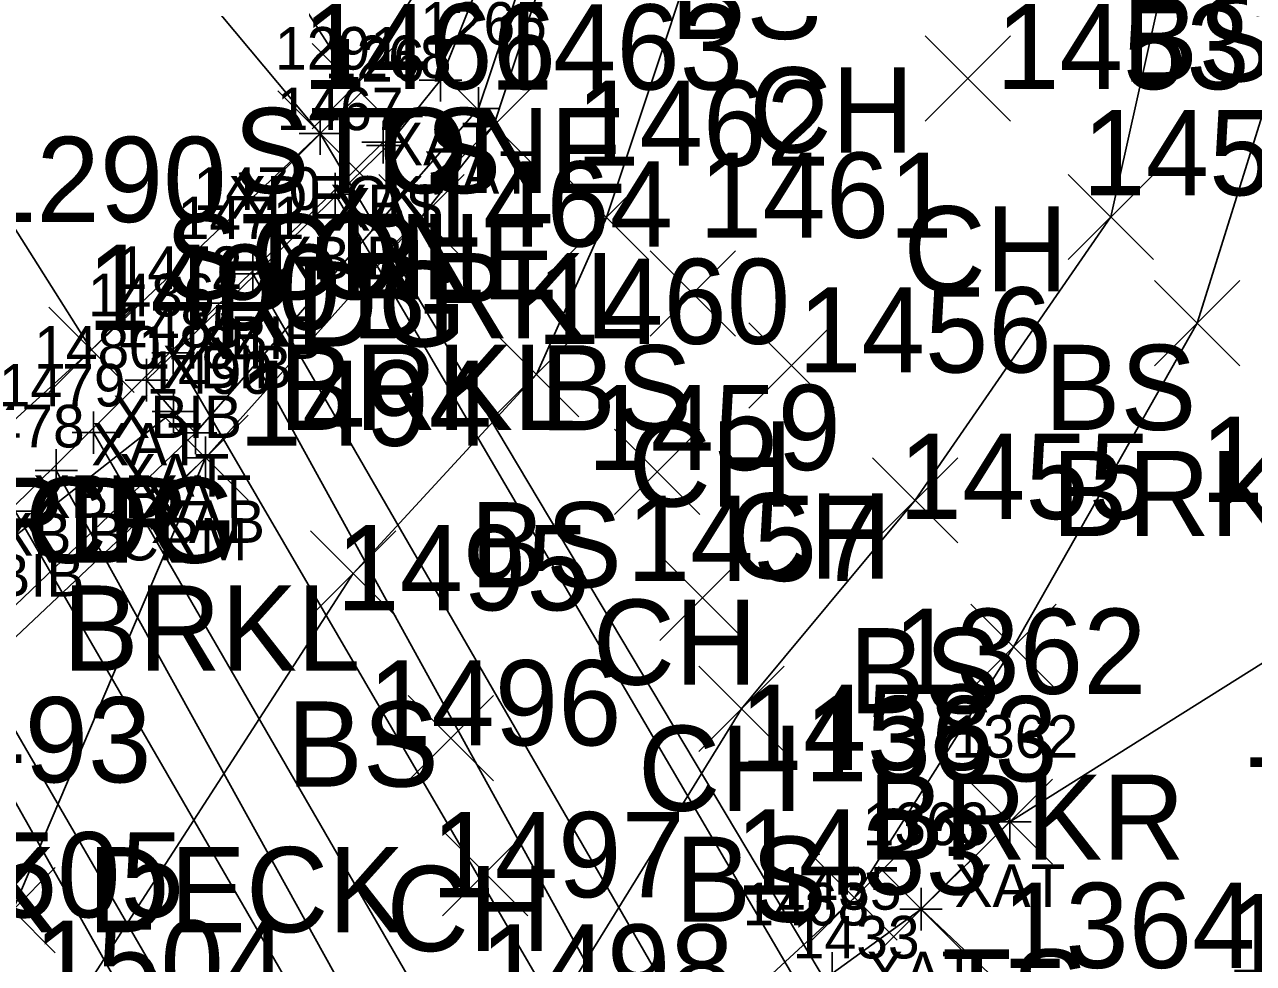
# Model space of a CAD drawing. Extents: x 1441651 to 1442140, y 243798 to 245625.
# Drawn here: x 1442046.7 to 1442075.54, y 245404.9 to 245426.94 of the extents above; entities that cross this region are included whole.
import ezdxf

# ---------------------------------------------------------------- set-up
doc = ezdxf.new("R2010")
doc.units = 0
for name, color, linetype in [('B_A', 7, 'Continuous'), ('B_C', 7, 'Continuous'), ('B_I', 7, 'Continuous'), ('B_TIC', 7, 'Continuous'), ('BB', 7, 'Continuous'), ('BELB', 7, 'Continuous'), ('BSE', 7, 'Continuous'), ('BSUBM', 7, 'Continuous'), ('L_A', 7, 'Continuous'), ('L_I', 7, 'Continuous'), ('L_TIC', 7, 'Continuous'), ('LASF', 7, 'Continuous'), ('LAWE', 7, 'Continuous'), ('LELB', 7, 'Continuous'), ('M_I', 7, 'Continuous'), ('P_A', 7, 'Continuous'), ('P_C', 7, 'Continuous'), ('P_I', 7, 'Continuous'), ('P_TIC', 7, 'Continuous'), ('PEU', 7, 'Continuous'), ('PRC', 7, 'Continuous'), ('R_A', 7, 'Continuous'), ('R_I', 7, 'Continuous'), ('R_TIC', 7, 'Continuous'), ('RGR', 7, 'Continuous')]:
    doc.layers.add(name, color=color, linetype=linetype)

msp = doc.modelspace()

# ---------------------------------------------------------------- linework, layer by layer
at = {"layer": 'B_TIC'}
for p, q in [((1442056.462, 245425.635), (1442056.538, 245425.635)), ((1442057.357, 245424.964), (1442057.433, 245424.964)), ((1442053.644, 245424.38), (1442053.72, 245424.38)), ((1442055.119, 245424.178), (1442055.195, 245424.178)), ((1442055.232, 245424.098), (1442055.307, 245424.098)), ((1442053.993, 245422.959), (1442054.069, 245422.959)), ((1442052.061, 245421.088), (1442052.136, 245421.088)), ((1442051.361, 245420.4), (1442051.436, 245420.4)), ((1442050.189, 245419.229), (1442050.265, 245419.229)), ((1442049.563, 245418.588), (1442049.639, 245418.588)), ((1442049.563, 245418.588), (1442049.639, 245418.588)), ((1442050.203, 245417.857), (1442050.278, 245417.857)), ((1442050.203, 245417.857), (1442050.278, 245417.857)), ((1442048.319, 245417.358), (1442048.395, 245417.358)), ((1442050.719, 245417.356), (1442050.794, 245417.356)), ((1442050.719, 245417.356), (1442050.794, 245417.356)), ((1442050.95, 245416.77), (1442051.026, 245416.77)), ((1442047.449, 245416.472), (1442047.525, 245416.472)), ((1442069.823, 245408.225), (1442069.899, 245408.225)), ((1442067.741, 245406.173), (1442067.816, 245406.173))]:
    msp.add_line(p, q, dxfattribs=at)
for points in [[(1442056.459, 245425.135), (1442056.459, 245426.135)], [(1442055.959, 245425.635), (1442056.959, 245425.635)], [(1442057.354, 245424.464), (1442057.354, 245425.464)], [(1442053.641, 245423.88), (1442053.641, 245424.88)], [(1442056.854, 245424.964), (1442057.854, 245424.964)], [(1442055.116, 245423.678), (1442055.116, 245424.678)], [(1442055.228, 245423.598), (1442055.228, 245424.598)], [(1442053.141, 245424.38), (1442054.141, 245424.38)], [(1442054.616, 245424.178), (1442055.616, 245424.178)], [(1442054.728, 245424.098), (1442055.728, 245424.098)], [(1442053.99, 245422.459), (1442053.99, 245423.459)], [(1442053.49, 245422.959), (1442054.49, 245422.959)], [(1442052.057, 245420.588), (1442052.057, 245421.588)], [(1442051.557, 245421.088), (1442052.557, 245421.088)], [(1442051.357, 245419.9), (1442051.357, 245420.9)], [(1442050.857, 245420.4), (1442051.857, 245420.4)], [(1442050.186, 245418.729), (1442050.186, 245419.729)], [(1442049.686, 245419.229), (1442050.686, 245419.229)], [(1442049.56, 245418.088), (1442049.56, 245419.088)], [(1442049.56, 245418.088), (1442049.56, 245419.088)], [(1442049.06, 245418.588), (1442050.06, 245418.588)], [(1442049.06, 245418.588), (1442050.06, 245418.588)], [(1442050.199, 245417.357), (1442050.199, 245418.357)], [(1442050.199, 245417.357), (1442050.199, 245418.357)], [(1442048.316, 245416.858), (1442048.316, 245417.858)], [(1442049.699, 245417.857), (1442050.699, 245417.857)], [(1442049.699, 245417.857), (1442050.699, 245417.857)], [(1442050.715, 245416.856), (1442050.715, 245417.856)], [(1442050.715, 245416.856), (1442050.715, 245417.856)], [(1442047.816, 245417.358), (1442048.816, 245417.358)], [(1442050.215, 245417.356), (1442051.215, 245417.356)], [(1442050.215, 245417.356), (1442051.215, 245417.356)], [(1442050.947, 245416.27), (1442050.947, 245417.27)], [(1442047.446, 245415.972), (1442047.446, 245416.972)], [(1442050.447, 245416.77), (1442051.447, 245416.77)], [(1442046.946, 245416.472), (1442047.946, 245416.472)], [(1442045.983, 245415.511), (1442046.983, 245415.511)], [(1442069.82, 245407.725), (1442069.82, 245408.725)], [(1442069.32, 245408.225), (1442070.32, 245408.225)], [(1442067.737, 245405.673), (1442067.737, 245406.673)], [(1442067.237, 245406.173), (1442068.237, 245406.173)], [(1442065.651, 245404.159), (1442065.651, 245405.159)], [(1442065.651, 245404.159), (1442065.651, 245405.159)]]:
    msp.add_lwpolyline(points, dxfattribs=at)
at = {"layer": 'BB'}
for points in [[(1442053.99, 245422.959), (1442064.918, 245404.29)], [(1442062.915, 245402.28), (1442052.057, 245421.088)], [(1442051.357, 245420.4), (1442061.877, 245401.279)], [(1442050.186, 245419.229), (1442061.127, 245400.457)], [(1442059.188, 245398.559), (1442048.316, 245417.358)], [(1442058.017, 245397.352), (1442047.446, 245416.472)], [(1442057.367, 245396.683), (1442046.483, 245415.511)], [(1442044.627, 245413.558), (1442055.528, 245394.741)]]:
    msp.add_lwpolyline(points, dxfattribs=at)
at = {"layer": 'BELB'}
for points in [[(1442053.641, 245424.38), (1442066.076, 245403.514)], [(1442043.134, 245414.629), (1442055.546, 245392.581)]]:
    msp.add_lwpolyline(points, dxfattribs=at)
at = {"layer": 'BSE'}
msp.add_lwpolyline([(1442055.116, 245424.178), (1442044.006, 245413.221)], dxfattribs=at)
at = {"layer": 'BSUBM'}
for points in [[(1442059.882, 245434.236), (1442060.401, 245434.055), (1442057.354, 245424.964), (1442050.715, 245417.356), (1442043.353, 245410.307), (1442039.483, 245407.236)], [(1442059.882, 245434.236), (1442056.459, 245425.635), (1442055.228, 245424.098), (1442049.56, 245418.588)], [(1442050.715, 245417.356), (1442050.199, 245417.857), (1442049.56, 245418.588)], [(1442050.199, 245417.857), (1442044.156, 245413.11), (1442042.328, 245411.507), (1442039.483, 245407.236)], [(1442050.947, 245416.77), (1442042.32, 245408.629), (1442039.483, 245407.236)], [(1442069.82, 245408.225), (1442067.737, 245406.173), (1442065.651, 245404.659)]]:
    msp.add_lwpolyline(points, dxfattribs=at)
at = {"layer": 'L_TIC'}
for points in [[(1442053.448, 245424.49), (1442055.448, 245426.49)], [(1442055.448, 245424.49), (1442053.448, 245426.49)], [(1442067.838, 245424.673), (1442069.838, 245426.673)], [(1442069.838, 245424.673), (1442067.838, 245426.673)], [(1442056.711, 245423.573), (1442058.711, 245425.573)], [(1442058.711, 245423.573), (1442056.711, 245425.573)], [(1442055.016, 245421.421), (1442057.016, 245423.421)], [(1442057.016, 245421.421), (1442055.016, 245423.421)], [(1442059.353, 245421.411), (1442061.353, 245423.411)], [(1442061.353, 245421.411), (1442059.353, 245423.411)], [(1442071.192, 245421.421), (1442073.192, 245423.421)], [(1442073.192, 245421.421), (1442071.192, 245423.421)], [(1442061.384, 245419.622), (1442063.384, 245421.622)], [(1442063.384, 245419.622), (1442061.384, 245421.622)], [(1442073.215, 245418.929), (1442075.215, 245420.929)], [(1442075.215, 245418.929), (1442073.215, 245420.929)], [(1442063.7, 245417.933), (1442065.7, 245419.933)], [(1442065.7, 245417.933), (1442063.7, 245419.933)], [(1442057.711, 245417.726), (1442059.711, 245419.726)], [(1442059.711, 245417.726), (1442057.711, 245419.726)], [(1442049.947, 245415.77), (1442051.947, 245417.77)], [(1442051.947, 245415.77), (1442049.947, 245417.77)], [(1442060.544, 245415.44), (1442062.544, 245417.44)], [(1442062.544, 245415.44), (1442060.544, 245417.44)], [(1442066.602, 245414.77), (1442068.602, 245416.77)], [(1442068.602, 245414.77), (1442066.602, 245416.77)], [(1442053.414, 245413.049), (1442055.414, 245415.049)], [(1442055.414, 245413.049), (1442053.414, 245415.049)], [(1442061.608, 245412.479), (1442063.608, 245414.479)], [(1442063.608, 245412.479), (1442061.608, 245414.479)], [(1442068.905, 245411.33), (1442070.905, 245413.33)], [(1442070.905, 245411.33), (1442068.905, 245413.33)], [(1442062.525, 245409.875), (1442064.525, 245411.875)], [(1442064.525, 245409.875), (1442062.525, 245411.875)], [(1442055.706, 245409.187), (1442057.706, 245411.187)], [(1442057.706, 245409.187), (1442055.706, 245411.187)], [(1442068.82, 245407.225), (1442070.82, 245409.225)], [(1442070.82, 245407.225), (1442068.82, 245409.225)], [(1442056.508, 245406.016), (1442058.508, 245408.016)], [(1442058.508, 245406.016), (1442056.508, 245408.016)], [(1442065.174, 245405.441), (1442067.174, 245407.441)], [(1442067.174, 245405.441), (1442065.174, 245407.441)], [(1442045.422, 245405.149), (1442047.422, 245407.149)], [(1442047.422, 245405.149), (1442045.422, 245407.149)], [(1442066.737, 245405.173), (1442068.737, 245407.173)], [(1442068.737, 245405.173), (1442066.737, 245407.173)]]:
    msp.add_lwpolyline(points, dxfattribs=at)
at = {"layer": 'LASF'}
msp.add_lwpolyline([(1442059.345, 245437.756), (1442056.061, 245427.98), (1442054.448, 245425.49)], dxfattribs=at)
at = {"layer": 'LAWE'}
for points in [[(1442099.331, 245492.7), (1442082.175, 245474.825), (1442073.962, 245459.556), (1442071.044, 245454.669), (1442067.5, 245447.08), (1442064.769, 245439.016), (1442060.82, 245433.995), (1442057.711, 245424.573), (1442056.016, 245422.421), (1442050.947, 245416.77), (1442046.422, 245406.149), (1442038.474, 245397.39), (1442032.995, 245390.022), (1442022.028, 245379.959), (1442015.438, 245373.014), (1442011.82, 245364.946), (1441999.311, 245341.928), (1441993.277, 245326.588), (1441983.696, 245301.797)], [(1442108.799, 245476.467), (1442096.827, 245461.697), (1442085.936, 245448.636), (1442079.446, 245435.792), (1442078.126, 245432.436), (1442074.215, 245419.929), (1442069.905, 245412.33), (1442066.174, 245406.441), (1442060.085, 245400.813), (1442053.875, 245394.968), (1442048.801, 245389.024), (1442033.753, 245369.5), (1442027.295, 245353.918), (1442016.143, 245332.931), (1442008.363, 245317.18), (1442000.261, 245295.499)]]:
    msp.add_lwpolyline(points, dxfattribs=at)
at = {"layer": 'LELB'}
for points in [[(1442102.458, 245487.565), (1442084.345, 245473.245), (1442077.162, 245458.74), (1442072.716, 245452.8), (1442069.733, 245445.651), (1442066.867, 245437.139), (1442063.415, 245431.599), (1442060.353, 245422.411), (1442058.711, 245418.726), (1442054.414, 245414.049), (1442047.261, 245402.979), (1442041.756, 245394.877), (1442035.105, 245387.217), (1442025.138, 245377.826), (1442014.243, 245362.921), (1442001.678, 245340.269), (1441995.167, 245325.255), (1441985.519, 245301.167)], [(1442107.479, 245478.045), (1442095.111, 245463.136), (1442085.124, 245450.231), (1442079.931, 245439.38), (1442074.016, 245430.6), (1442072.192, 245422.421), (1442067.602, 245415.77), (1442063.525, 245410.875), (1442058.938, 245403.451), (1442051.468, 245396.66), (1442047.361, 245390.552), (1442031.625, 245371.637), (1442024.894, 245355.937), (1442013.328, 245334.791), (1442005.478, 245318.663), (1441997.832, 245296.612)], [(1442080.914, 245421.582), (1442076.992, 245412.732), (1442069.82, 245408.225)], [(1442067.737, 245406.173), (1442072.375, 245401.791)]]:
    msp.add_lwpolyline(points, dxfattribs=at)
at = {"layer": 'P_TIC'}
for points in [[(1442052.641, 245423.38), (1442054.641, 245425.38)], [(1442054.641, 245423.38), (1442052.641, 245425.38)], [(1442052.641, 245423.38), (1442054.641, 245425.38)], [(1442054.641, 245423.38), (1442052.641, 245425.38)], [(1442047.272, 245418.302), (1442049.272, 245420.302)], [(1442049.272, 245418.302), (1442047.272, 245420.302)], [(1442047.272, 245418.302), (1442049.272, 245420.302)], [(1442049.272, 245418.302), (1442047.272, 245420.302)]]:
    msp.add_lwpolyline(points, dxfattribs=at)
at = {"layer": 'PEU'}
for points in [[(1441949.699, 245598.806), (1441965.584, 245568.638), (1441979.812, 245540.541), (1441994.499, 245512.774), (1442011.015, 245488.252), (1442024.854, 245464.866), (1442045.339, 245434.299), (1442053.641, 245424.38)], [(1441937.939, 245591.884), (1441953.89, 245562.719), (1441968.906, 245535.694), (1441984.797, 245506.977), (1441992.987, 245492.297), (1442013.076, 245458.975), (1442024.733, 245444.52), (1442043.134, 245414.629), (1442048.272, 245419.302), (1442053.641, 245424.38)]]:
    msp.add_lwpolyline(points, dxfattribs=at)
at = {"layer": 'PRC'}
msp.add_lwpolyline([(1441943.372, 245595.219), (1441959.061, 245565.314), (1441973.709, 245538.049), (1441989.919, 245509.625), (1442005.514, 245485.136), (1442020.379, 245462.654), (1442040.921, 245430.942), (1442048.272, 245419.302)], dxfattribs=at)
at = {"layer": 'R_TIC'}
for points in [[(1442053.448, 245424.49), (1442055.448, 245426.49)], [(1442055.448, 245424.49), (1442053.448, 245426.49)]]:
    msp.add_lwpolyline(points, dxfattribs=at)
at = {"layer": 'RGR'}
msp.add_lwpolyline([(1442043.563, 245442.549), (1442054.448, 245425.49)], dxfattribs=at)

# ---------------------------------------------------------------- texts
at = {"layer": 'B_A'}
for s, p in [('XAT', (1442055.164, 245423.635)), ('XAT', (1442056.058, 245422.964)), ('XDECK', (1442051.483, 245422.38)), ('XBS', (1442053.856, 245422.178)), ('XAT', (1442053.933, 245422.098)), ('XBIB', (1442052.561, 245420.959)), ('XBIB', (1442050.628, 245419.088)), ('XBIB', (1442049.928, 245418.4)), ('XBIB', (1442048.757, 245417.229)), ('XAT', (1442048.265, 245416.588)), ('XAT', (1442048.265, 245416.588)), ('XAT', (1442048.904, 245415.857)), ('XAT', (1442048.904, 245415.857)), ('XBIB', (1442046.887, 245415.358)), ('XAT', (1442049.42, 245415.356)), ('XAT', (1442049.42, 245415.356)), ('XAB', (1442049.667, 245414.77)), ('XBIB', (1442046.017, 245414.472)), ('XBIB', (1442045.054, 245413.511)), ('XAT', (1442068.524, 245406.225)), ('XAT', (1442066.442, 245404.173))]:
    msp.add_text(s, height=1, dxfattribs=at).set_placement(p)
at = {"layer": 'B_C'}
msp.add_text('CRM', height=1, dxfattribs=at).set_placement((1442048.884, 245414.357))
msp.add_text('CRM', height=1, dxfattribs=at).set_placement((1442048.884, 245414.357))
at = {"layer": 'B_I'}
for s, p in [('1265', (1442055.983, 245426.464)), ('1291', (1442052.578, 245425.88)), ('1268', (1442053.746, 245425.678)), ('1267', (1442053.858, 245425.598)), ('1467', (1442052.62, 245424.459)), ('1470', (1442050.668, 245422.588)), ('1471', (1442050.294, 245421.9)), ('1472', (1442048.839, 245420.729)), ('1486', (1442048.186, 245420.088)), ('1486', (1442048.186, 245420.088)), ('1485', (1442048.853, 245419.357)), ('1485', (1442048.853, 245419.357)), ('1480', (1442046.926, 245418.858)), ('1484', (1442049.369, 245418.856)), ('1484', (1442049.369, 245418.856)), ('1490', (1442049.557, 245418.27)), ('1479', (1442046.096, 245417.972)), ('1478', (1442045.137, 245417.011)), ('1362', (1442068.45, 245409.725)), ('1363', (1442066.367, 245407.673)), ('1435', (1442064.305, 245406.159)), ('1435', (1442064.305, 245406.159)), ('1468', (1442063.548, 245405.79)), ('1433', (1442064.729, 245405.014))]:
    msp.add_text(s, height=1, dxfattribs=at).set_placement(p)
at = {"layer": 'L_A'}
for s, p in [('BS', (1442061.855, 245426.599)), ('BS', (1442072.457, 245425.6)), ('CH', (1442063.705, 245423.933)), ('STONE', (1442051.604, 245422.98)), ('TS', (1442054.471, 245422.98)), ('CH', (1442067.326, 245420.673)), ('STONE', (1442049.992, 245420.49)), ('BRKL', (1442054.357, 245419.573)), ('BRKL', (1442052.662, 245417.421)), ('BS', (1442058.794, 245417.411)), ('BS', (1442070.633, 245417.421)), ('CH', (1442060.872, 245415.622)), ('BRKR', (1442070.806, 245414.929)), ('CH', (1442063.189, 245413.933)), ('BS', (1442057.152, 245413.726)), ('BRKL', (1442047.593, 245411.77)), ('CH', (1442060.032, 245411.44)), ('BS', (1442066.043, 245410.77)), ('BS', (1442052.855, 245409.049)), ('CH', (1442061.096, 245408.479)), ('TS', (1442075.402, 245407.732)), ('BRKR', (1442066.496, 245407.33)), ('BS', (1442061.966, 245405.875)), ('CH', (1442055.194, 245405.187)), ('TS', (1442068.229, 245403.225))]:
    msp.add_text(s, height=2, dxfattribs=at).set_placement(p)
at = {"layer": 'L_I'}
for s, p in [('1466', (1442053.221, 245425.421)), ('1463', (1442057.613, 245425.411)), ('1453', (1442069.5, 245425.421)), ('1462', (1442059.644, 245423.622)), ('1454', (1442071.522, 245422.929)), ('1461', (1442062.527, 245421.933)), ('1464', (1442055.971, 245421.726)), ('1490', (1442048.167, 245419.77)), ('1460', (1442058.717, 245419.44)), ('1456', (1442064.854, 245418.77)), ('1494', (1442051.722, 245417.049)), ('1459', (1442059.907, 245416.479)), ('1359', (1442074.291, 245415.732)), ('1359', (1442074.291, 245415.732)), ('1359', (1442074.291, 245415.732)), ('1455', (1442067.212, 245415.33)), ('1457', (1442060.833, 245413.875)), ('1495', (1442054.013, 245413.187)), ('1362', (1442067.079, 245411.225)), ('1496', (1442054.76, 245410.016)), ('1458', (1442063.481, 245409.441)), ('1493', (1442043.729, 245409.149)), ('1363', (1442064.997, 245409.173)), ('1497', (1442056.245, 245406.451)), ('1505', (1442044.489, 245405.979)), ('1364', (1442069.635, 245404.791)), ('1364', (1442069.635, 245404.791)), ('1504', (1442046.914, 245403.904)), ('1498', (1442057.392, 245403.813))]:
    msp.add_text(s, height=2, dxfattribs=at).set_placement(p)
at = {"layer": 'M_I'}
msp.add_text('1434', height=2, dxfattribs=at).set_placement((1442074.887, 245404.531))
at = {"layer": 'P_A'}
for s, p in [('RDG', (1442051.129, 245419.38)), ('RDG', (1442051.129, 245419.38)), ('RDG', (1442045.76, 245414.302)), ('CR', (1442046.705, 245414.302))]:
    msp.add_text(s, height=2, dxfattribs=at).set_placement(p)
at = {"layer": 'P_C'}
msp.add_text('WOOD PLANK DECK', height=2, dxfattribs=at).set_placement((1442029.308, 245405.629))
at = {"layer": 'P_I'}
for s, p in [('1290', (1442045.492, 245422.302)), ('1290', (1442045.492, 245422.302)), ('1433', (1442063.383, 245406.514)), ('1433', (1442063.383, 245406.514))]:
    msp.add_text(s, height=2, dxfattribs=at).set_placement(p)
at = {"layer": 'R_A'}
msp.add_text('GRL', height=2, dxfattribs=at).set_placement((1442051.992, 245420.49))
at = {"layer": 'R_I'}
msp.add_text('1433', height=2, dxfattribs=at).set_placement((1442063.383, 245406.514))

doc.saveas('drawing.dxf')
